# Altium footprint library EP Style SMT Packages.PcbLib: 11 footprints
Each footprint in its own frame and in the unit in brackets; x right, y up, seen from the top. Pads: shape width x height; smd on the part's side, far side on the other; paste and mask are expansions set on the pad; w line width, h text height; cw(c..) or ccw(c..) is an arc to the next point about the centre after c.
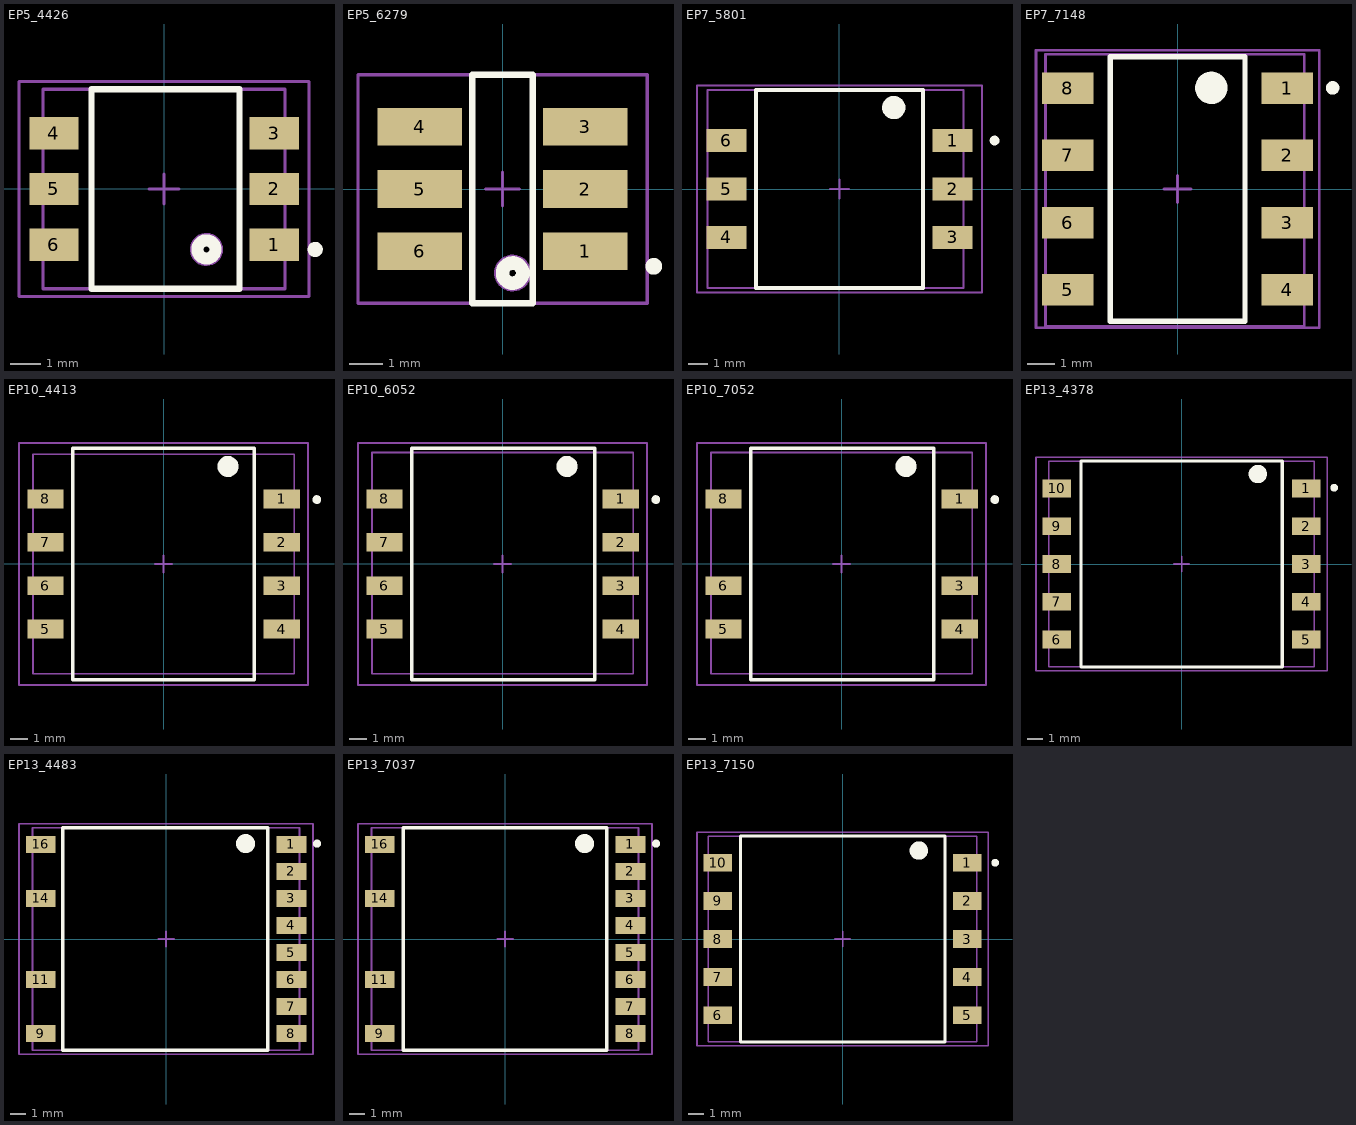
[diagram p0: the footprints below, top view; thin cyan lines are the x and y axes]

## EP5_4426 [mm] "SMD, 6-Leads, Body 6.60x8.26mm, Pitch 1.85mm, IPC Medium Density"
height 5.59
pads (6):
  rect 1.63x1.07 smd: 1(3.645,-1.85) 2(3.645,0) 3(3.645,1.85) 4(-3.645,1.85) 5(-3.645,0) 6(-3.645,-1.85)
Top Overlay:
  circle w0.25: c5,-2 r0.125
  circle w0.4: c1.4,-2 r0.3
  lines w0.2: -2.4,-3.3 -2.4,3.3 2.5,3.3 2.5,-3.3 -2.4,-3.3
Mechanical 13:
  circle w0.1: c1.4,-2 r0.5
  lines w0.1: -4,-3.3 -4,3.3 4,3.3 4,-3.3 -4,-3.3
Mechanical 15:
  lines w0.1: -0.5,0 0.5,0 ; 0,-0.5 0,0.5 ; -4.8,-3.55 -4.8,3.55 4.8,3.55 4.8,-3.55 -4.8,-3.55
  text ".Designator" at 0,0 h0.5
3D body "070-4426.stp": height 5.11, standoff -0.04, extent -3.85,-3.235 3.85,3.235

## EP5_6279 [mm] "SMD, 6-Leads, Body 7.00x9.10mm, Pitch 1.85mm, IPC Medium Density"
height 7.8
pads (6):
  rect 2.52x1.12 smd: 1(2.465,-1.85) 2(2.465,0) 3(2.465,1.85) 4(-2.465,1.85) 5(-2.465,0) 6(-2.465,-1.85)
Top Overlay:
  circle w0.25: c4.5,-2.3 r0.125
  circle w0.4: c0.3,-2.5 r0.3
  lines w0.2: -0.9,-3.4 -0.9,3.4 0.9,3.4 0.9,-3.4 -0.9,-3.4
Mechanical 13:
  circle w0.1: c0.3,-2.5 r0.5
  lines w0.1: -4.3,-3.4 -4.3,3.4 4.3,3.4 4.3,-3.4 -4.3,-3.4
Mechanical 15:
  lines w0.1: -0.5,0 0.5,0 ; 0,-0.5 0,0.5 ; -4.3,-3.4 -4.3,3.4 4.3,3.4 4.3,-3.4 -4.3,-3.4
  text ".Designator" at 0,0 h0.5
3D body "STEP-070-6279.step": height 7.63, standoff 0.02, extent -4.2,-3.2 4.2,3.27

## EP7_5801 [mm] "SMD, 6-Leads, Body 10.16x13.36mm, Pitch 2.50mm, IPC Medium Density"
height 8.64
pads (6):
  rect 2.08x1.17 smd: 1(5.83,2.5) 2(5.83,0) 3(5.83,-2.5) 4(-5.83,-2.5) 5(-5.83,0) 6(-5.83,2.5)
Top Overlay:
  circle w0.6: c2.8,4.2 r0.3
  circle w0.25: c8,2.5 r0.125
  lines w0.2: -4.3,-5.1 4.3,-5.1 4.3,5.1 -4.3,5.1 -4.3,-5.1
Mechanical 13:
  circle w0.1: c2.8,4.2 r0.5
  lines w0.1: -6.8,-5.1 6.4,-5.1 6.4,5.1 -6.8,5.1 -6.8,-5.1
Mechanical 15:
  lines w0.1: -0.5,0 0.5,0 ; 0,-0.5 0,0.5 ; -7.35,-5.35 7.35,-5.35 7.35,5.35 -7.35,5.35 -7.35,-5.35
  text ".Designator" at 0,0 h0.5
3D body "070-5801.stp": height 8.61, standoff 0.02, extent -6.55,-4.92 6.15,4.9

## EP7_7148 [mm] "SMD, 8-Leads, Body 9.78x9.14mm, Pitch 2.49mm, IPC Medium Density"
height 10.54
pads (8):
  rect 1.91x1.17 smd: 1(4.065,3.735) 2(4.065,1.245) 3(4.065,-1.245) 4(4.065,-3.735) 5(-4.065,-3.735) 6(-4.065,-1.245) 7(-4.065,1.245) 8(-4.065,3.735)
Top Overlay:
  circle w0.6: c1.25,3.75 r0.3
  circle w0.25: c5.75,3.75 r0.125
  lines w0.2: -2.5,-4.9 2.5,-4.9 2.5,4.9 -2.5,4.9 -2.5,-4.9
Mechanical 13:
  circle w0.1: c1.25,3.75 r0.5
  lines w0.1: -4.9,-5.1 4.7,-5.1 4.7,5 -4.9,5 -4.9,-5.1
Mechanical 15:
  lines w0.1: -0.5,0 0.5,0 ; 0,-0.5 0,0.5 ; -5.25,-5.15 5.25,-5.15 5.25,5.15 -5.25,5.15 -5.25,-5.15
  text ".Designator" at 0,0 h0.5
3D body "070-4436.stp": height 10.1, standoff 0.01, extent -4.68,-4.97 4.48,4.85

## EP10_4413 [mm] "SMD, 8-Leads, Body 13.34x15.24mm, Pitch 2.49mm, IPC Medium Density"
height 11.56
pads (8):
  rect 2.08x1.07 smd: 1(6.78,3.735) 2(6.78,1.245) 3(6.78,-1.245) 4(6.78,-3.735) 5(-6.78,-3.735) 6(-6.78,-1.245) 7(-6.78,1.245) 8(-6.78,3.735)
Top Overlay:
  circle w0.25: c8.8,3.7 r0.125
  circle w0.6: c3.7,5.6 r0.3
  lines w0.2: -5.2,-6.65 -5.2,6.65 5.2,6.65 5.2,-6.65 -5.2,-6.65
Mechanical 13:
  circle w0.1: c3.7,5.6 r0.5
  lines w0.1: -7.5,-6.3 -7.5,6.3 7.5,6.3 7.5,-6.3 -7.5,-6.3
Mechanical 15:
  lines w0.1: -0.5,0 0.5,0 ; 0,-0.5 0,0.5 ; -8.3,-6.95 -8.3,6.95 8.3,6.95 8.3,-6.95 -8.3,-6.95
  text ".Designator" at 0,0 h0.5
3D body "070-4410.stp": height 11.05, standoff 0.03, extent -7.3,-6.1 7.3,6.03

## EP10_6052 [mm] "SMD, 8-Leads, Body 13.34x15.24mm, Pitch 2.49mm, IPC Medium Density"
height 11.43
pads (8):
  rect 2.08x1.07 smd: 1(6.78,3.735) 2(6.78,1.245) 3(6.78,-1.245) 4(6.78,-3.735) 5(-6.78,-3.735) 6(-6.78,-1.245) 7(-6.78,1.245) 8(-6.78,3.735)
Top Overlay:
  circle w0.6: c3.7,5.6 r0.3
  circle w0.25: c8.8,3.7 r0.125
  lines w0.2: -5.2,-6.65 5.3,-6.65 5.3,6.65 -5.2,6.65 -5.2,-6.65
Mechanical 13:
  circle w0.1: c3.7,5.6 r0.5
  lines w0.1: -7.5,-6.3 7.5,-6.3 7.5,6.4 -7.5,6.4 -7.5,-6.3
Mechanical 15:
  lines w0.1: -0.5,0 0.5,0 ; 0,-0.5 0,0.5 ; -8.3,-6.95 8.3,-6.95 8.3,6.95 -8.3,6.95 -8.3,-6.95
  text ".Designator" at 0,0 h0.5
3D body "070-6052.stp": height 10.8, standoff 0.02, extent -7.31,-6 7.31,6.13

## EP10_7052 [mm] "SMD, 8-Leads, Body 13.34x15.24mm, Pitch 2.49mm, IPC Medium Density"
height 11.43
pads (6):
  rect 2.08x1.07 smd: 1(6.78,3.735) 3(6.78,-1.245) 4(6.78,-3.735) 5(-6.78,-3.735) 6(-6.78,-1.245) 8(-6.78,3.735)
Top Overlay:
  circle w0.6: c3.7,5.6 r0.3
  circle w0.25: c8.8,3.7 r0.125
  lines w0.2: -5.2,-6.65 5.3,-6.65 5.3,6.65 -5.2,6.65 -5.2,-6.65
Mechanical 13:
  circle w0.1: c3.7,5.6 r0.5
  lines w0.1: -7.5,-6.3 7.5,-6.3 7.5,6.4 -7.5,6.4 -7.5,-6.3
Mechanical 15:
  lines w0.1: -0.5,0 0.5,0 ; 0,-0.5 0,0.5 ; -8.3,-6.95 8.3,-6.95 8.3,6.95 -8.3,6.95 -8.3,-6.95
  text ".Designator" at 0,0 h0.5
3D body "070-6052.stp": height 10.8, standoff 0.02, extent -7.31,-6 7.31,6.13

## EP13_4378 [mm] "SMD, 10-Leads, Body 13.46x17.75mm, Pitch 2.48mm, IPC Medium Density"
height 12.7
pads (10):
  rect 1.88x1.17 smd: 1(8.18,4.96) 2(8.18,2.48) 3(8.18,0) 4(8.18,-2.48) 5(8.18,-4.96) 6(-8.18,-4.96) 7(-8.18,-2.48) 8(-8.18,0) 9(-8.18,2.48) 10(-8.18,4.96)
Top Overlay:
  circle w0.25: c10,5 r0.125
  circle w0.6: c5,5.9 r0.3
  lines w0.2: -6.6,-6.75 -6.6,6.75 6.6,6.75 6.6,-6.75 -6.6,-6.75
Mechanical 13:
  circle w0.1: c5,5.9 r0.5
  lines w0.1: -8.7,-6.75 -8.7,6.75 8.7,6.75 8.7,-6.75 -8.7,-6.75
Mechanical 15:
  lines w0.1: -0.5,0 0.5,0 ; 0,-0.5 0,0.5 ; -9.55,-7 -9.55,7 9.55,7 9.55,-7 -9.55,-7
  text ".Designator" at 0,0 h0.5
3D body "EP13_4375.step": height 12.27, standoff 0, extent -8.5,-6.5 8.5,6.6

## EP13_4483 [mm] "SMD, 16-Leads, Body 13.97x17.17mm, Pitch 1.70mm, IPC Medium Density"
height 12.7
pads (12):
  rect 1.88x1.07 smd: 1(7.885,5.95) 2(7.885,4.25) 3(7.885,2.55) 4(7.885,0.85) 5(7.885,-0.85) 6(7.885,-2.55) 7(7.885,-4.25) 8(7.885,-5.95) 9(-7.885,-5.95) 11(-7.885,-2.55) 14(-7.885,2.55) 16(-7.885,5.95)
Top Overlay:
  circle w0.25: c9.5,6 r0.125
  circle w0.6: c5,6 r0.3
  lines w0.2: -6.5,-7 -6.5,7 6.4,7 6.4,-7 -6.5,-7
Mechanical 13:
  circle w0.1: c5,6 r0.5
  lines w0.1: -8.4,-7 -8.4,7 8.4,7 8.4,-7 -8.4,-7
Mechanical 15:
  lines w0.1: -0.5,0 0.5,0 ; 0,-0.5 0,0.5 ; -9.25,-7.25 -9.25,7.25 9.25,7.25 9.25,-7.25 -9.25,-7.25
  text ".Designator" at 0,0 h0.5
3D body "070-4482.stp": height 12.23, standoff -0.04, extent -8.21,-6.8 8.21,6.84

## EP13_7037 [mm] "SMD, 16-Leads, Body 13.97x17.17mm, Pitch 1.70mm, IPC Medium Density"
height 12.7
pads (12):
  rect 1.88x1.07 smd: 1(7.885,5.95) 2(7.885,4.25) 3(7.885,2.55) 4(7.885,0.85) 5(7.885,-0.85) 6(7.885,-2.55) 7(7.885,-4.25) 8(7.885,-5.95) 9(-7.885,-5.95) 11(-7.885,-2.55) 14(-7.885,2.55) 16(-7.885,5.95)
Top Overlay:
  circle w0.6: c5,6 r0.3
  circle w0.25: c9.5,6 r0.125
  lines w0.2: -6.4,-7 6.4,-7 6.4,7 -6.4,7 -6.4,-7
Mechanical 13:
  circle w0.1: c5,6 r0.5
  lines w0.1: -8.4,-7 8.4,-7 8.4,7 -8.4,7 -8.4,-7
Mechanical 15:
  lines w0.1: -0.5,0 0.5,0 ; 0,-0.5 0,0.5 ; -9.25,-7.25 9.25,-7.25 9.25,7.25 -9.25,7.25 -9.25,-7.25
  text ".Designator" at 0,0 h0.5
3D body "070-4482.stp": height 12.23, standoff -0.04, extent -8.21,-6.8 8.21,6.84

## EP13_7150 [mm] "SMD, 10-Leads, Body 13.46x17.75mm, Pitch 2.50mm, IPC Medium Density"
height 12.7
pads (10):
  rect 1.88x1.17 smd: 1(8.18,5) 2(8.18,2.5) 3(8.18,0) 4(8.18,-2.5) 5(8.18,-5) 6(-8.18,-5) 7(-8.18,-2.5) 8(-8.18,0) 9(-8.18,2.5) 10(-8.18,5)
Top Overlay:
  circle w0.25: c10,5 r0.125
  circle w0.6: c5,5.8 r0.3
  lines w0.2: -6.7,-6.75 -6.7,6.75 6.7,6.75 6.7,-6.75 -6.7,-6.75
Mechanical 13:
  circle w0.1: c5,5.8 r0.5
  lines w0.1: -8.8,-6.75 -8.8,6.75 8.8,6.75 8.8,-6.75 -8.8,-6.75
Mechanical 15:
  lines w0.1: -0.5,0 0.5,0 ; 0,-0.5 0,0.5 ; -9.55,-7 -9.55,7 9.55,7 9.55,-7 -9.55,-7
  text ".Designator" at 0,0 h0.5
3D body "070-5465.stp": height 12, standoff 0.04, extent -8.58,-6.56 8.58,6.56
